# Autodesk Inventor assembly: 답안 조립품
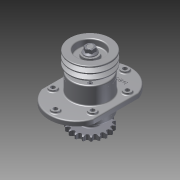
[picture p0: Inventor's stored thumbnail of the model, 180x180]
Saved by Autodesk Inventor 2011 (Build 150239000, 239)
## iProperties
Created: 2015-02
Part Number: 답안 조립품
Document SubType Name: Assembly
Designer: Administrator
Author: Administrator
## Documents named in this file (12)
- C:\Documents and Settings\Administrator\바탕 화면\450207V1021\답안 조립품.iam
- C:\Documents and Settings\Administrator\바탕 화면\450207V1021\본체.ipt
- C:\Documents and Settings\Administrator\바탕 화면\450207V1021\2-커버.ipt
- C:\Documents and Settings\Administrator\바탕 화면\450207V1021\8-오일실 30x42.ipt
- C:\Documents and Settings\Administrator\바탕 화면\450207V1021\6-베어링 6206.ipt
- C:\Documents and Settings\Administrator\바탕 화면\450207V1021\10-M6.ipt
- C:\Documents and Settings\Administrator\바탕 화면\450207V1021\3-축.ipt
- C:\Documents and Settings\Administrator\바탕 화면\450207V1021\7-부시.ipt
- C:\Documents and Settings\Administrator\바탕 화면\450207V1021\11-키 6x6.ipt
- C:\Documents and Settings\Administrator\바탕 화면\450207V1021\4-V벨트풀리.ipt
- C:\Documents and Settings\Administrator\바탕 화면\450207V1021\9-M16-너트.ipt
- C:\Documents and Settings\Administrator\바탕 화면\450207V1021\5-체인 스프로킷.ipt
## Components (22 placed, 10 different names)
1. 2-커버:1
2. 2-커버:2
3. 8-8-오일실 30x42:1
4. 8-8-오일실 30x42:2
5. 6-베어링 6206:1
6. 6-베어링 6206:2
7. 3-축:1
8. 7-부시:1
9. 11-키 6x6:1
10. 11-키 6x6:2
11. 4-V벨트풀리:1
12. 9-M16 너트:1 — 각도:3
13. 9-M16 너트:2 — 각도:4
14. 5-체인 스프로킷:1
15. 10-M6:2 — 각도:1
16. 10-M6:3
17. 10-M6:4
18. 10-M6:5
19. 10-M6:1 — 각도:2
20. 10-M6:6
21. 10-M6:7
22. 10-M6:8
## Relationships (4: Angle 4)
- 각도:1 [Angle]: 10-M6:2
- 각도:2 [Angle]: 10-M6:1
- 각도:3 [Angle]: 9-M16 너트:1
- 각도:4 [Angle]: 9-M16 너트:2
